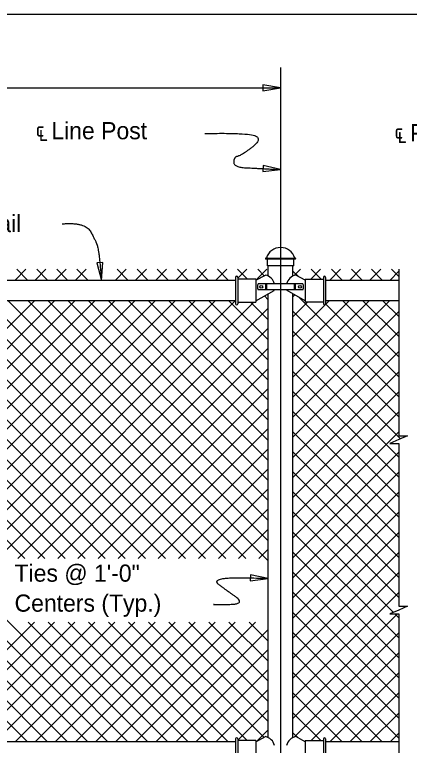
# Model space of a CAD drawing. Extents: x 110698 to 110915, y 110390 to 110472.
# Drawn here: x 110793.02 to 110797.65, y 110456.22 to 110464.8 of the extents above; entities that cross this region are included whole.
import ezdxf

# ---------------------------------------------------------------- set-up
doc = ezdxf.new("R2010")
doc.units = 0
for name, color, linetype in [('ActivePts-ConstElements', 7, 'Continuous'), ('AdhocPoint_dp', 7, 'Continuous'), ('Border', 7, 'Continuous'), ('PlotBorder_dp', 7, 'Continuous'), ('SheetBorder_dp', 7, 'Continuous'), ('TextMisc', 7, 'Continuous')]:
    doc.layers.add(name, color=color, linetype=linetype)

msp = doc.modelspace()

# ---------------------------------------------------------------- linework, layer by layer
at = {"layer": 'ActivePts-ConstElements'}
msp.add_lwpolyline([(110774.0658, 110438.856), (110815.1163, 110438.856), (110815.1163, 110464.8021), (110774.0658, 110464.8021)], close=True, dxfattribs=at)
at = {"layer": 'AdhocPoint_dp'}
msp.add_line((110796.1408, 110464.1815), (110796.1408, 110455.3996), dxfattribs=at)
at = {"layer": 'PlotBorder_dp'}
msp.add_line((110776.1407, 110463.9443), (110796.1408, 110463.9443), dxfattribs=at)
for points in [[(110796.1408, 110463.9444), (110795.9326, 110463.9797), (110795.9326, 110463.9091)], [(110796.1408, 110462.9833), (110795.9348, 110463.0299), (110795.9309, 110462.9595)], [(110794.0382, 110461.6831), (110794.0539, 110461.8938), (110793.9837, 110461.8872)], [(110795.9951, 110458.1843), (110795.7884, 110458.2281), (110795.7856, 110458.1576)]]:
    msp.add_lwpolyline(points, close=True, dxfattribs=at)
for points in [[(110797.5278, 110461.8153), (110797.5278, 110459.8591), (110797.6311, 110459.8591), (110797.5278, 110459.8141), (110797.4245, 110459.7691), (110797.5278, 110459.7691), (110797.5278, 110458.8754)], [(110797.5278, 110458.8754), (110797.5278, 110457.8577), (110797.6311, 110457.8577), (110797.5278, 110457.8127), (110797.4245, 110457.7677), (110797.5278, 110457.7677), (110797.5278, 110455.8133)]]:
    msp.add_lwpolyline(points, dxfattribs=at)
for points in [[(110795.2513, 110463.4071), (110795.797, 110463.4169), (110795.9195, 110463.328), (110795.6753, 110463.1467), (110795.5904, 110463.1283), (110795.5904, 110463.0104), (110795.8685, 110462.9982), (110796.1408, 110462.9833)], [(110793.5763, 110462.3461), (110793.8479, 110462.3685), (110793.9742, 110462.1414), (110794.0109, 110462.0198), (110794.0381, 110461.683)], [(110795.3625, 110457.8796), (110795.319, 110457.8796), (110795.7391, 110457.8796), (110795.4889, 110458.0567), (110795.3517, 110458.1594), (110795.5622, 110458.2019), (110795.995, 110458.1841)]]:
    msp.add_open_spline(points, degree=2, dxfattribs=at)
at = {"layer": 'SheetBorder_dp'}
for p, q in [((110793.0213, 110461.6831), (110793.1514, 110461.8133)), ((110793.044, 110461.8133), (110793.1742, 110461.6831)), ((110793.257, 110461.6831), (110793.3871, 110461.8133)), ((110793.2797, 110461.8133), (110793.4099, 110461.6831)), ((110793.4927, 110461.6831), (110793.6228, 110461.8133)), ((110793.5154, 110461.8133), (110793.6456, 110461.6831)), ((110793.7284, 110461.6831), (110793.8585, 110461.8133)), ((110793.7511, 110461.8133), (110793.8813, 110461.6831)), ((110794.1998, 110461.6831), (110794.3299, 110461.8133)), ((110794.2225, 110461.8133), (110794.3527, 110461.6831)), ((110794.4355, 110461.6831), (110794.5656, 110461.8133)), ((110794.4582, 110461.8133), (110794.5884, 110461.6831)), ((110794.6712, 110461.6831), (110794.8013, 110461.8133)), ((110794.6939, 110461.8133), (110794.8241, 110461.6831)), ((110794.9069, 110461.6831), (110795.0371, 110461.8133)), ((110794.9296, 110461.8133), (110795.0598, 110461.6831)), ((110795.1426, 110461.6831), (110795.2728, 110461.8133)), ((110795.1653, 110461.8133), (110795.2955, 110461.6831)), ((110795.3783, 110461.6831), (110795.5085, 110461.8133)), ((110795.401, 110461.8133), (110795.5312, 110461.6831)), ((110795.6367, 110461.8133), (110795.7515, 110461.6985)), ((110795.6382, 110461.7073), (110795.7442, 110461.8133)), ((110795.8512, 110461.6846), (110795.9799, 110461.8133)), ((110795.8724, 110461.8133), (110795.9482, 110461.7375)), ((110796.2866, 110461.7924), (110796.3518, 110461.7272)), ((110796.2986, 110461.7386), (110796.3732, 110461.8133)), ((110796.4942, 110461.6985), (110796.6089, 110461.8133)), ((110796.5015, 110461.8133), (110796.6162, 110461.6985)), ((110796.7145, 110461.6831), (110796.8446, 110461.8133)), ((110796.7372, 110461.8133), (110796.8674, 110461.6831)), ((110796.9502, 110461.6831), (110797.0803, 110461.8133)), ((110796.9729, 110461.8133), (110797.1031, 110461.6831)), ((110797.1859, 110461.6831), (110797.316, 110461.8133)), ((110797.2086, 110461.8133), (110797.3388, 110461.6831)), ((110797.4216, 110461.6831), (110797.5277, 110461.7892)), ((110797.4443, 110461.8133), (110797.5277, 110461.7298)), ((110796.2866, 110461.491), (110796.3079, 110461.5122)), ((110789.2545, 110456.2664), (110794.4316, 110461.4435)), ((110789.4902, 110456.2664), (110794.6673, 110461.4435)), ((110789.7259, 110456.2664), (110794.903, 110461.4435)), ((110789.9616, 110456.2664), (110795.1387, 110461.4435)), ((110790.1973, 110456.2664), (110795.3744, 110461.4435)), ((110790.433, 110456.2664), (110795.6114, 110461.4448)), ((110790.6687, 110456.2664), (110795.8286, 110461.4263)), ((110790.821, 110461.4435), (110793.8469, 110458.4176)), ((110791.0567, 110461.4435), (110794.0826, 110458.4176)), ((110791.2924, 110461.4435), (110794.3183, 110458.4176)), ((110791.5281, 110461.4435), (110794.554, 110458.4176)), ((110791.7638, 110461.4435), (110794.7897, 110458.4176)), ((110791.8926, 110460.083), (110793.2531, 110461.4435)), ((110791.9995, 110461.4435), (110795.0254, 110458.4176)), ((110792.1283, 110460.083), (110793.4888, 110461.4435)), ((110792.2315, 110459.9505), (110793.7245, 110461.4435)), ((110792.2315, 110459.4791), (110794.1959, 110461.4435)), ((110792.2315, 110459.7148), (110793.9602, 110461.4435)), ((110792.2352, 110461.4435), (110795.2611, 110458.4176)), ((110792.4709, 110461.4435), (110795.4968, 110458.4176)), ((110792.7066, 110461.4435), (110795.7325, 110458.4176)), ((110792.9423, 110461.4435), (110795.995, 110458.3909)), ((110793.178, 110461.4435), (110795.995, 110458.6266)), ((110793.4137, 110461.4435), (110795.995, 110458.8623)), ((110793.6494, 110461.4435), (110795.995, 110459.098)), ((110793.8851, 110461.4435), (110795.995, 110459.3337)), ((110794.1208, 110461.4435), (110795.995, 110459.5694)), ((110794.3565, 110461.4435), (110795.995, 110459.8051)), ((110794.5923, 110461.4435), (110795.995, 110460.0408)), ((110794.828, 110461.4435), (110795.995, 110460.2765)), ((110795.0637, 110461.4435), (110795.995, 110460.5122)), ((110795.2994, 110461.4435), (110795.995, 110460.7479)), ((110795.5351, 110461.4435), (110795.995, 110460.9836)), ((110795.788, 110461.4263), (110795.995, 110461.2193)), ((110795.9505, 110461.4994), (110795.995, 110461.455)), ((110796.2866, 110460.3125), (110797.4177, 110461.4435)), ((110796.2866, 110460.5482), (110797.182, 110461.4435)), ((110796.2866, 110461.0196), (110796.7106, 110461.4435)), ((110796.2866, 110461.2553), (110796.4577, 110461.4263)), ((110796.2911, 110460.7883), (110796.9463, 110461.4435)), ((110796.36, 110461.4834), (110797.5277, 110460.3156)), ((110796.8712, 110461.4435), (110797.5277, 110460.787)), ((110797.1069, 110461.4435), (110797.5277, 110461.0227)), ((110797.3426, 110461.4435), (110797.5277, 110461.2584)), ((110793.0556, 110458.4176), (110795.995, 110461.357)), ((110796.6701, 110461.4089), (110797.5277, 110460.5513)), ((110796.2866, 110461.321), (110797.5277, 110460.0799)), ((110796.2866, 110460.0768), (110797.5277, 110461.3178)), ((110793.2913, 110458.4176), (110795.995, 110461.1213)), ((110796.2866, 110461.0853), (110797.5488, 110459.8231)), ((110796.2866, 110459.8411), (110797.5277, 110461.0821)), ((110793.527, 110458.4176), (110795.995, 110460.8856)), ((110796.2866, 110460.8496), (110797.5277, 110459.6085)), ((110796.2866, 110459.6054), (110797.5277, 110460.8464)), ((110793.7627, 110458.4176), (110795.995, 110460.6499)), ((110796.2866, 110460.6139), (110797.5277, 110459.3728)), ((110796.2866, 110459.3696), (110797.5277, 110460.6107)), ((110793.9984, 110458.4176), (110795.995, 110460.4142)), ((110796.2866, 110460.3782), (110797.5277, 110459.1371)), ((110796.2866, 110459.1339), (110797.5277, 110460.375)), ((110794.2341, 110458.4176), (110795.995, 110460.1785)), ((110796.2866, 110460.1425), (110797.5277, 110458.9014)), ((110796.2866, 110458.8982), (110797.5277, 110460.1393)), ((110794.4698, 110458.4176), (110795.995, 110459.9428)), ((110796.2866, 110459.9068), (110797.5277, 110458.6657)), ((110796.2866, 110458.6625), (110797.5277, 110459.9036)), ((110792.2315, 110459.7974), (110793.6112, 110458.4176)), ((110794.7055, 110458.4176), (110795.995, 110459.7071)), ((110796.2866, 110459.6711), (110797.5277, 110458.43)), ((110796.2866, 110458.4268), (110797.5277, 110459.6679)), ((110792.2315, 110459.5617), (110793.3755, 110458.4176)), ((110794.9412, 110458.4176), (110795.995, 110459.4714)), ((110796.2866, 110459.4354), (110797.5277, 110458.1943)), ((110796.2866, 110458.1911), (110797.5277, 110459.4322)), ((110790.0705, 110459.3656), (110793.1697, 110456.2664)), ((110790.3062, 110459.3656), (110793.4054, 110456.2664)), ((110790.5419, 110459.3656), (110793.6411, 110456.2664)), ((110790.7776, 110459.3656), (110793.8768, 110456.2664)), ((110791.0133, 110459.3656), (110794.1125, 110456.2664)), ((110791.249, 110459.3656), (110794.3482, 110456.2664)), ((110792.1918, 110459.3656), (110793.1398, 110458.4176)), ((110795.1769, 110458.4176), (110795.995, 110459.2357)), ((110796.2866, 110459.1997), (110797.5277, 110457.9586)), ((110796.2866, 110457.9554), (110797.5277, 110459.1965)), ((110795.4126, 110458.4176), (110795.995, 110459)), ((110796.2866, 110458.964), (110797.4652, 110457.7854)), ((110796.2866, 110457.7197), (110797.5277, 110458.9608)), ((110795.6483, 110458.4176), (110795.995, 110458.7642)), ((110796.2866, 110458.7283), (110797.5277, 110457.4872)), ((110796.2866, 110457.484), (110797.5277, 110458.7251)), ((110795.884, 110458.4176), (110795.995, 110458.5285)), ((110796.2866, 110458.4926), (110797.5277, 110457.2515)), ((110796.2866, 110457.2483), (110797.5277, 110458.4894)), ((110796.2866, 110458.2569), (110797.5277, 110457.0158)), ((110796.2866, 110457.0126), (110797.5277, 110458.2537)), ((110796.2866, 110458.0212), (110797.5277, 110456.7801)), ((110796.2866, 110456.7769), (110797.5277, 110458.018)), ((110796.2866, 110457.7855), (110797.5277, 110456.5444)), ((110796.2866, 110456.5412), (110797.5131, 110457.7676)), ((110797.483, 110457.7676), (110797.5277, 110457.7229)), ((110791.8472, 110456.2664), (110793.2529, 110457.6721)), ((110792.0829, 110456.2664), (110793.4886, 110457.6721)), ((110792.3186, 110456.2664), (110793.7243, 110457.6721)), ((110792.5543, 110456.2664), (110793.96, 110457.6721)), ((110792.79, 110456.2664), (110794.1957, 110457.6721)), ((110793.0257, 110456.2664), (110794.4314, 110457.6721)), ((110793.1782, 110457.6721), (110794.5839, 110456.2664)), ((110793.2614, 110456.2664), (110794.6671, 110457.6721)), ((110793.414, 110457.6721), (110794.8196, 110456.2664)), ((110793.4971, 110456.2664), (110794.9028, 110457.6721)), ((110793.6497, 110457.6721), (110795.0553, 110456.2664)), ((110793.7328, 110456.2664), (110795.1385, 110457.6721)), ((110793.8854, 110457.6721), (110795.291, 110456.2664)), ((110793.9685, 110456.2664), (110795.3742, 110457.6721)), ((110794.1211, 110457.6721), (110795.5267, 110456.2664)), ((110794.2042, 110456.2664), (110795.6099, 110457.6721)), ((110794.3568, 110457.6721), (110795.747, 110456.2818)), ((110794.4399, 110456.2664), (110795.8456, 110457.6721)), ((110794.5925, 110457.6721), (110795.9454, 110456.3192)), ((110794.8282, 110457.6721), (110795.995, 110456.5052)), ((110795.0639, 110457.6721), (110795.995, 110456.7409)), ((110795.2996, 110457.6721), (110795.995, 110456.9766)), ((110795.5353, 110457.6721), (110795.995, 110457.2123)), ((110795.771, 110457.6721), (110795.995, 110457.4481)), ((110794.6756, 110456.2664), (110795.995, 110457.5857)), ((110796.2866, 110457.5498), (110797.5277, 110456.3087)), ((110796.3056, 110456.3244), (110797.5277, 110457.5466)), ((110794.9113, 110456.2664), (110795.995, 110457.35)), ((110796.2866, 110457.3141), (110797.3343, 110456.2664)), ((110796.4986, 110456.2818), (110797.5277, 110457.3109)), ((110795.147, 110456.2664), (110795.995, 110457.1143)), ((110796.2866, 110457.0784), (110797.0986, 110456.2664)), ((110796.7189, 110456.2664), (110797.5277, 110457.0752)), ((110795.3827, 110456.2664), (110795.995, 110456.8786)), ((110796.2866, 110456.8427), (110796.8629, 110456.2664)), ((110796.9546, 110456.2664), (110797.5277, 110456.8395)), ((110795.6382, 110456.2862), (110795.995, 110456.6429)), ((110796.2866, 110456.607), (110796.6118, 110456.2818)), ((110797.1903, 110456.2664), (110797.5277, 110456.6038)), ((110795.8593, 110456.2715), (110795.995, 110456.4072)), ((110796.2866, 110456.3712), (110796.3419, 110456.316)), ((110797.426, 110456.2664), (110797.5277, 110456.3681))]:
    msp.add_line(p, q, dxfattribs=at)
at = {"layer": 'TextMisc'}
for p, q in [((110795.9685, 110461.9452), (110796.3131, 110461.9452)), ((110796.3131, 110461.933), (110795.9685, 110461.933)), ((110795.9867, 110461.8532), (110795.9867, 110461.933)), ((110796.2949, 110461.8532), (110796.2949, 110461.933)), ((110796.2949, 110461.8532), (110795.9867, 110461.8532)), ((110795.995, 110461.7333), (110795.995, 110461.8532)), ((110796.2866, 110461.7333), (110796.2866, 110461.8532)), ((110795.6114, 110461.6831), (110786.6701, 110461.6831)), ((110795.6114, 110461.7181), (110795.6114, 110461.4084)), ((110795.6383, 110461.7181), (110795.6383, 110461.4084)), ((110795.8512, 110461.6985), (110795.6383, 110461.6985)), ((110795.8512, 110461.6838), (110795.9621, 110461.7452)), ((110795.8512, 110461.6985), (110795.8512, 110461.4263)), ((110796.4303, 110461.6838), (110796.3195, 110461.7452)), ((110796.4303, 110461.6985), (110796.4303, 110461.4263)), ((110796.4303, 110461.6985), (110796.6433, 110461.6985)), ((110796.6433, 110461.7181), (110796.6433, 110461.4084)), ((110796.6701, 110461.7181), (110796.6701, 110461.4084)), ((110797.5278, 110461.6831), (110796.6701, 110461.6831)), ((110796.4031, 110461.6412), (110795.8784, 110461.6412)), ((110795.9608, 110461.6334), (110795.9842, 110461.6334)), ((110795.9608, 110461.6238), (110795.9842, 110461.6238)), ((110795.9608, 110461.613), (110795.9842, 110461.613)), ((110795.9608, 110461.6012), (110795.9842, 110461.6012)), ((110796.3208, 110461.6334), (110796.2973, 110461.6334)), ((110796.3208, 110461.6238), (110796.2973, 110461.6238)), ((110796.3208, 110461.613), (110796.2973, 110461.613)), ((110796.3208, 110461.6012), (110796.2973, 110461.6012)), ((110795.8512, 110461.4444), (110796.0652, 110461.563)), ((110796.4031, 110461.5734), (110795.8784, 110461.5734)), ((110795.9608, 110461.5894), (110795.9842, 110461.5894)), ((110795.9608, 110461.5796), (110795.9842, 110461.5796)), ((110795.995, 110456.3166), (110795.995, 110461.5241)), ((110796.4303, 110461.4444), (110796.2164, 110461.563)), ((110796.2866, 110456.3166), (110796.2866, 110461.524)), ((110796.3208, 110461.5894), (110796.2973, 110461.5894)), ((110796.3208, 110461.5796), (110796.2973, 110461.5796)), ((110795.6114, 110461.4435), (110786.6701, 110461.4435)), ((110795.6383, 110461.4263), (110795.8512, 110461.4263)), ((110796.6433, 110461.4263), (110796.4303, 110461.4263)), ((110797.5278, 110461.4435), (110796.6701, 110461.4435)), ((110795.6114, 110456.3014), (110795.6114, 110455.9917)), ((110795.6383, 110456.3014), (110795.6383, 110455.9917)), ((110795.8512, 110456.2818), (110795.6383, 110456.2818)), ((110795.8512, 110456.2671), (110795.9621, 110456.3284)), ((110795.8512, 110456.2818), (110795.8512, 110456.0096)), ((110796.4303, 110456.2671), (110796.3195, 110456.3284)), ((110796.4303, 110456.2818), (110796.4303, 110456.0096)), ((110796.4303, 110456.2818), (110796.6433, 110456.2818)), ((110796.6433, 110456.3014), (110796.6433, 110455.9917)), ((110796.6701, 110456.3014), (110796.6701, 110455.9917)), ((110795.6114, 110456.2664), (110786.6701, 110456.2664)), ((110797.5278, 110456.2664), (110796.6701, 110456.2664))]:
    msp.add_line(p, q, dxfattribs=at)
for centre, radius, start, end in [((110795.9686, 110461.9389), 0.00613, 91.1647, 268.8353), ((110796.3129, 110461.9389), 0.00613, 271.1647, 88.8353), ((110795.6249, 110461.718), 0.0134, 0, 180), ((110796.6566, 110461.718), 0.0134, 0, 180), ((110795.6249, 110461.4082), 0.0134, 180, 0), ((110796.6566, 110461.4082), 0.0134, 180, 0), ((110795.6249, 110456.3013), 0.0134, 0, 180), ((110796.6566, 110456.3013), 0.0134, 0, 180)]:
    msp.add_arc(centre, radius, start, end, dxfattribs=at)
for centre, major_axis, start_param, end_param in [((110796.1415, 110461.9042), (0.1711, 0), 0.252602, 2.888574), ((110795.9276, 110461.6092), (0.146, 0), 0.231126, 1.331255), ((110796.354, 110461.6092), (-0.146, 0), 4.95193, 6.05206), ((110795.9475, 110461.6072), (-0.0776, 0), 5.810211, 6.75616), ((110796.334, 110461.6072), (0.0776, 0), 5.810211, 6.75616), ((110795.9276, 110461.6092), (0.146, 0), 5.947976, 6.024627), ((110796.354, 110461.6092), (-0.146, 0), 0.258558, 0.335209), ((110795.9276, 110456.1925), (0.146, 0), 0.231126, 1.331255), ((110796.354, 110456.1925), (-0.146, 0), 4.95193, 6.05206)]:
    msp.add_ellipse(centre, major_axis=major_axis, ratio=0.957868, start_param=start_param, end_param=end_param, dxfattribs=at)
for centre, major_axis in [((110795.9142, 110461.6068), (0.0178, 0)), ((110796.3673, 110461.6068), (-0.0178, 0))]:
    msp.add_ellipse(centre, major_axis=major_axis, ratio=0.957868, dxfattribs=at)

# ---------------------------------------------------------------- texts
at = {"layer": 'Border'}
for s, p in [('℄ Line Post', (110793.266, 110463.3389)), ('℄ Pull Post', (110797.4771, 110463.3149)), ('Horizontal Rail', (110791.3454, 110462.2491))]:
    msp.add_text(s, height=0.2016, dxfattribs=at).set_placement(p)
at = {"layer": 'PlotBorder_dp'}
for s, p in [('Ties @ 1\'-0" ', (110793.0186, 110458.1458)), ('Centers (Typ.)', (110793.0186, 110457.7938))]:
    msp.add_text(s, height=0.2016, dxfattribs=at).set_placement(p)

doc.saveas('drawing.dxf')
